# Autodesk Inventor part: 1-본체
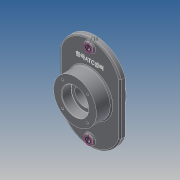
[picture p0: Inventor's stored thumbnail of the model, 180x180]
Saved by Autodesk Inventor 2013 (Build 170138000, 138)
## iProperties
Created: 2015-02
Part Number: 1-본체
Material: 일반
Document SubType Name: Modeling
Designer: kb543-18
Density: 1 g/cm^3
Mass: 603.771 g
Surface Area: 900.498 cm^2
Volume: 603.771 cm^3
Author: kb543-18
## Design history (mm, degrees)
sketch "스케치1"
  geometry: L1 (-70, -60)-(-70, 60); L2 (70, 60)-(70, -60); L3 (70, -60)-(-70, 60); L4 (-70, -60)-(70, 60); L5 (-70, 60)-(70, 60); L6 (-70, -60)-(70, -60); A1 r 74 centre (0, 36) between (70, 60) and (-70, 60); A2 r 74 centre (0, -36) between (-70, -60) and (70, -60); 2 further points
  constraints: 12 end point, 4 point on circle, 2 centre point, 2 parallel, 1 coincident, 1 equal radius, 1 horizontal, 1 midpoint, 1 perpendicular
  dimensions: "d0" = 120 distance of L2.start L2.end; "d2" = 140 distance of L1.end L2.start; "d3" = 50 distance edge to line of A1 L5
extrude "돌출1" new body sketch "스케치1" distance "d5" = 12; taper "d6" = 0 deg
node "작업 평면2"
sketch "스케치3"
  geometry: C1 r 50 at (0, 0); C2 r 31 at (0, 0); C3 r 22.5 at (0, 0); 1 further point
  constraints: 3 centre point, 3 coincident
  dimensions: "d8" = 100 diameter of C1; "d10" = 62 diameter of C2; "d11" = 45 diameter of C3
extrude "돌출2" join sketch "스케치3" distance "d12" = 70; taper "d13" = 0 deg
extrude "돌출3" cut sketch "스케치3" distance "d14" = 22; taper "d15" = 0 deg
extrude "돌출4" cut sketch "스케치3" distance "d16" = 70; taper "d17" = 0 deg
sketch "스케치4"
  geometry: C1 r 22.5 at (0, 0) reference; C2 r 50 at (0, 0) reference; C3 r 31 at (0, 0)
  constraints: 1 centre point, 1 coincident
  dimensions: "d18" = 62 diameter of C3
extrude "돌출5" cut sketch "스케치4" distance "d20" = 22; taper "d21" = 0 deg
sketch "스케치5"
  geometry: L1 (-70, -60)-(-70, 60) reference; L2 (70, 60)-(70, -60) reference; L3 (-53, 56.976)-(-53, -56.976); L4 (53, -56.976)-(53, 56.976); C1 r 10 at (0, 93); C2 r 10 at (0, -93); C3 r 5.5 at (0, -93); A1 r 74 centre (0, -36) between (-70, -60) and (70, -60) reference; A2 r 74 centre (0, 36) between (70, 60) and (-70, 60) reference; A3 r 57 centre (0, -36) between (-53, -56.976) and (53, -56.976); A4 r 57 centre (0, 36) between (53, 56.976) and (-53, 56.976); 2 further points
  constraints: 6 point on circle, 5 centre point, 4 end point, 3 coincident, 1 equal radius, 3 other
  dimensions: "d22" = 17 distance between parallel lines of L2 L4; "d23" = 20 diameter of C1; "d30" = 11 diameter of C3
extrude "돌출6" join sketch "스케치5" distance "d24" = 5; taper "d25" = 0 deg
sketch "스케치6"
  geometry: C1 r 10 at (0, 0) reference; C2 r 5.5 at (0, 0); C3 r 10 at (0, -186) reference; C4 r 5.5 at (0, -186); 1 further point
  constraints: 2 centre point, 2 coincident
  dimensions: "d26" = 11 diameter of C2; "d31" = 11 diameter of C4
  node "투영된 루프1"
extrude "돌출7" cut sketch "스케치6" stored distance "d28" = 5; taper "d29" = 0 deg
sketch "스케치7"
  geometry: L1 (0, 0)-(0, 41); L2 (0, 0)-(28.991, 28.991); C1 r 50 at (0, 0) reference; C2 r 50 at (0, 0) reference; A1 r 41 centre (0, 0) between (28.991, 28.991) and (0, 41); 1 further point
  constraints: 4 end point, 2 coincident, 2 point on circle, 1 centre point, 1 vertical
  dimensions: "d32" = 45 deg angle of L1 L2; "d33" = 82 diameter of A1
node "작업 평면3"
sketch "스케치8"
  geometry: C1 r 50 at (0, 0) reference; 1 further point
  constraints: 1 vertical alignment, 1 other
  dimensions: "d44" = 65 distance of point (0, 65) C1.centre
feature "엠보싱1" sketch "스케치8" dims "d0" = 120, "d2" = 140, "d3" = 50, "d45" = 1, "d46" = 0
fillet "모깎기1" dims "d47" = 3
chamfer "모따기1" distance "d48" = 1; stored, may be unused: second distance "d49" = 2, angle "d50" = 45 deg
fillet "모깎기2" dims "d51" = 0.3
hole "구멍2" sketch "스케치7" diameter "d52" = 4.917; stored, may be unused: countersink angle "d56" = 90 deg, drill point angle "d58" = 118 deg; dims "d53" = 10, "d54" = 4, "d55" = 2, "d57" = 13
node "작업 평면4"
node "솔리드1"
pattern_circular "원형 패턴2" dims angle "d60" = 360 deg
mirror "대칭2"
other parameters: "d7" = 23
